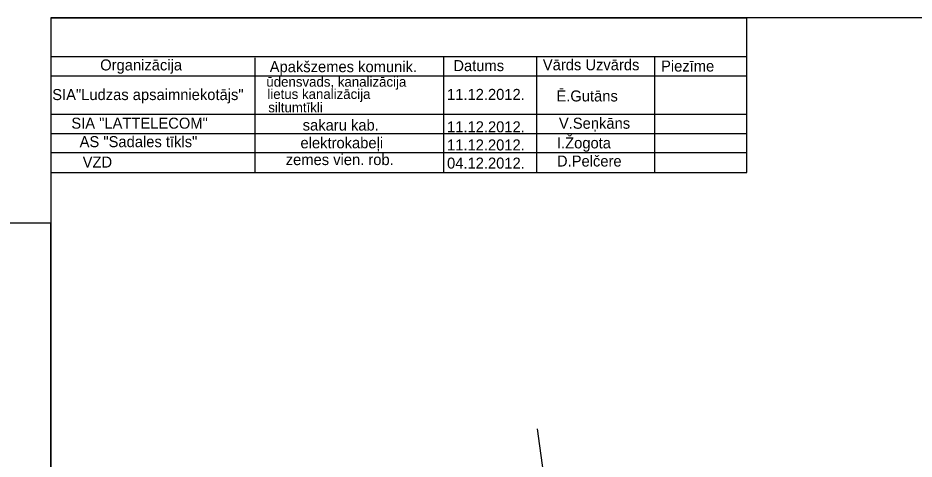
# Model space of a CAD drawing. Extents: x 728492 to 729038, y 272968 to 273171.
# Drawn here: x 728762.3 to 728843.7, y 273130.8 to 273170.9 of the extents above; entities that cross this region are included whole.
import ezdxf

# ---------------------------------------------------------------- set-up
doc = ezdxf.new("R2010")
doc.units = 0
doc.layers.add('APGR_SARK_####_####_#', color=7, linetype='Continuous')
doc.layers.add('RAMI_PLAN_####_TKST_#', color=7, linetype='Continuous')

msp = doc.modelspace()

# ---------------------------------------------------------------- linework, layer by layer
at = {"layer": 'APGR_SARK_####_####_#'}
msp.add_lwpolyline([(728809.481, 273133.58), (728813.011, 273107.831)], dxfattribs=at)
at = {"layer": 'RAMI_PLAN_####_TKST_#'}
for p, q in [((728765.305, 273170.927), (728828.53, 273170.926)), ((728765.305, 273167.424), (728828.53, 273167.424)), ((728783.871, 273156.882), (728783.871, 273167.293)), ((728800.998, 273156.882), (728800.998, 273167.424)), ((728809.448, 273156.882), (728809.448, 273167.336)), ((728820.18, 273156.882), (728820.18, 273167.38)), ((728765.305, 273165.678), (728828.53, 273165.678)), ((728765.305, 273162.186), (728828.53, 273162.186)), ((728765.305, 273160.44), (728828.53, 273160.44)), ((728765.305, 273158.695), (728828.53, 273158.694)), ((728765.305, 273156.882), (728828.53, 273156.882))]:
    msp.add_line(p, q, dxfattribs=at)
for points in [[(728765.305, 273170.927), (728765.305, 272986.902), (729038.383, 272986.902), (729038.383, 273170.927)], [(728492.227, 273152.288), (728492.227, 272968.263), (728765.305, 272968.263), (728765.305, 273152.288)]]:
    msp.add_lwpolyline(points, close=True, dxfattribs=at)
for points in [[(728765.305, 273170.927), (728765.305, 273152.948)], [(728828.53, 273156.882), (728828.53, 273170.926)]]:
    msp.add_lwpolyline(points, dxfattribs=at)

# ---------------------------------------------------------------- texts
for s, height, rotation, p in [('Organizācija', 1, 359.99995, (728769.796, 273166.155)), ('Datums', 1, 359.99995, (728801.868, 273166.093)), ('Vārds Uzvārds', 1, 359.99995, (728809.995, 273166.17)), ('Piezīme', 1, 359.99995, (728820.73, 273166.057)), ('Apakšzemes komunik.', 1, 359.99995, (728785.191, 273165.998)), ('ūdensvads, kanalizācija', 0.9, 359.99986, (728784.885, 273164.678)), ('SIA"Ludzas apsaimniekotājs"', 1, 359.99972, (728765.44, 273163.462)), ('lietus kanalizācija', 0.9, 359.99972, (728784.978, 273163.561)), ('11.12.2012.', 1, 359.99995, (728801.295, 273163.479)), ('Ē.Gutāns', 1, 359.99972, (728811.228, 273163.338)), ('siltumtīkli', 0.9, 359.99972, (728785.062, 273162.346)), ('SIA "LATTELECOM"', 1, 359.99972, (728767.176, 273160.864)), ('sakaru kab.', 1, 359.99995, (728788.185, 273160.695)), ('11.12.2012.', 1, 359.99995, (728801.295, 273160.532)), ('V.Seņkāns', 1, 359.99972, (728811.454, 273160.858)), ('AS "Sadales tīkls"', 1, 359.99972, (728767.929, 273159.184)), ('elektrokabeļi', 1, 359.99972, (728787.983, 273159.079)), ('11.12.2012.', 1, 359.99995, (728801.295, 273158.884)), ('I.Žogota', 1, 359.99972, (728811.277, 273159.071)), ('VZD', 1, 359.99972, (728768.204, 273157.331)), ('zemes vien. rob.', 1, 359.99972, (728786.644, 273157.556)), ('04.12.2012.', 1, 359.99995, (728801.295, 273157.236)), ('D.Pelčere', 1, 359.99972, (728811.277, 273157.424))]:
    msp.add_text(s, height=height, rotation=rotation, dxfattribs=at).set_placement(p)

doc.saveas('drawing.dxf')
